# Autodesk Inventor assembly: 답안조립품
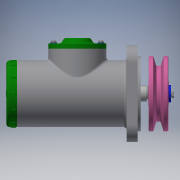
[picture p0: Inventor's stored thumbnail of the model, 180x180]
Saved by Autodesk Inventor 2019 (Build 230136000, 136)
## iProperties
Created: 2021-07
Part Number: 답안조립품
Material: 일반
Document SubType Name: Assembly
Designer: jun-2-7
Author: jun-2-7
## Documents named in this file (20)
- C:\Users\jun-2-7\Desktop\710706V1020\답안조립품.iam
- C:\Users\jun-2-7\Desktop\710706V1020\본체.ipt
- C:\Users\jun-2-7\Desktop\710706V1020\사이드 커버.ipt
- 사이드 커버.ipt
- C:\Users\jun-2-7\Desktop\710706V1020\축.ipt
- C:\Users\jun-2-7\Desktop\710706V1020\멈춤링 15 x 1.ipt
- C:\Users\jun-2-7\Desktop\710706V1020\베어링 15 x 35 x 11.ipt
- C:\Users\jun-2-7\Desktop\710706V1020\부시1.ipt
- C:\Users\jun-2-7\Desktop\710706V1020\부시2.ipt
- C:\Users\jun-2-7\Desktop\710706V1020\멈춤링 35 x 1.6.ipt
- C:\Users\jun-2-7\Desktop\710706V1020\와셔 10 x 21.ipt
- C:\Users\jun-2-7\Desktop\710706V1020\너트 M10.ipt
- C:\Users\jun-2-7\Desktop\710706V1020\오일 실 15 25 7.ipt
- C:\Users\jun-2-7\Desktop\710706V1020\키 4 x 4 x 18.ipt
- C:\Users\jun-2-7\Desktop\710706V1020\V-벨트풀리.ipt
- C:\Users\jun-2-7\Desktop\710706V1020\와셔 4 x 16.ipt
- C:\Users\jun-2-7\Desktop\710706V1020\볼트 M4 x 10.ipt
- C:\Users\jun-2-7\Desktop\710706V1020\탑 커버.ipt
- C:\Users\jun-2-7\Desktop\710706V1020\와셔 3 x 6.ipt
- C:\Users\jun-2-7\Desktop\710706V1020\십자볼트 M3 x 10.ipt
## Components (2 placed, 2 different names)
1. V-벨트풀리:1
2. ISO 4017 M4 x 10:1
